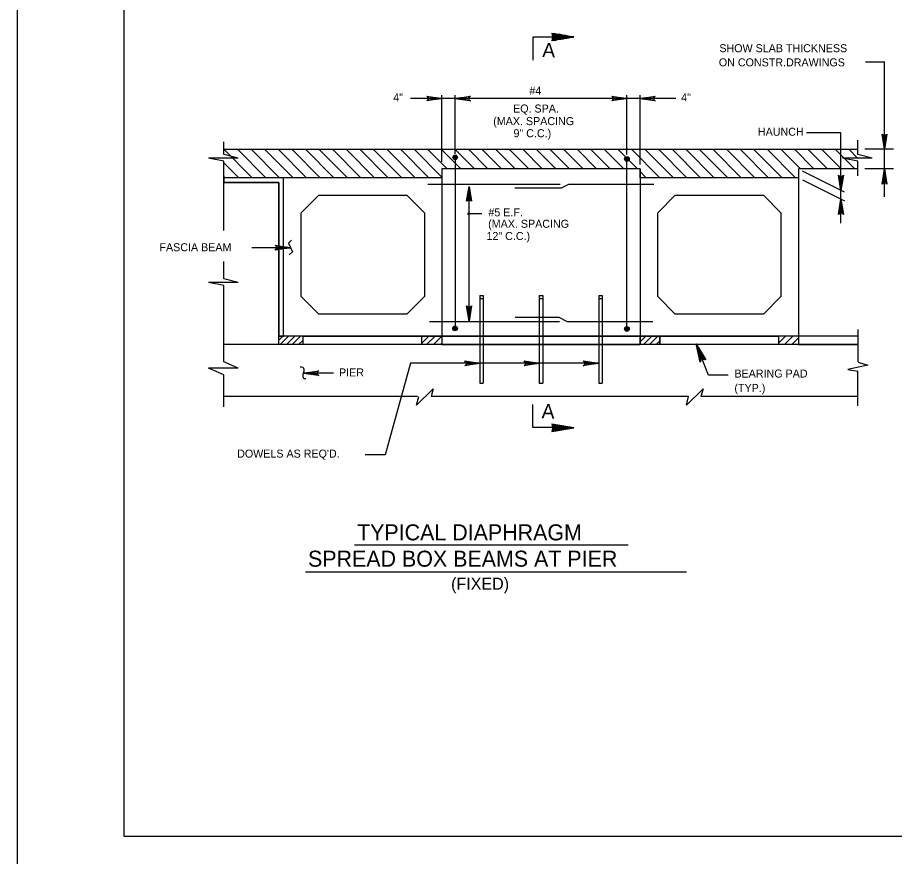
# Model space of a CAD drawing. Extents: x 641517 to 642372, y 298537 to 300319.
# Drawn here: x 641517 to 641845.7, y 299732.1 to 300046.6 of the extents above; entities that cross this region are included whole.
import ezdxf

# ---------------------------------------------------------------- set-up
doc = ezdxf.new("R2010")
doc.units = 0
doc.layers.add('2', color=7, linetype='Continuous')
doc.layers.add('PLT-BNDY', color=7, linetype='Continuous')

msp = doc.modelspace()

# ---------------------------------------------------------------- linework, layer by layer
at = {"layer": '2'}
for p, q in [((641557.05, 299739.62), (641557.05, 300303.62)), ((641722.01, 300039.19), (641710.17, 300039.22)), ((641710.17, 300039.22), (641710.17, 300030.64)), ((641834.82, 300029.95), (641841.96, 300029.95)), ((641841.96, 299997.22), (641841.96, 300029.95)), ((641681.07, 300016.27), (641664.27, 300016.27)), ((641676.12, 299992.57), (641676.12, 300017.47)), ((641681.07, 299995.57), (641681.07, 300017.47)), ((641745.42, 300016.27), (641681.07, 300016.27)), ((641745.42, 299995.27), (641745.42, 300017.47)), ((641763.72, 300016.27), (641745.42, 300016.27)), ((641750.37, 299991.52), (641750.37, 300017.47)), ((641825.67, 300003.45), (641812.71, 300003.45)), ((641825.67, 299969.47), (641825.67, 300003.45)), ((641594.37, 299995.27), (641594.37, 300000.07)), ((641831.97, 299995.27), (641831.97, 300000.67)), ((641594.37, 299997.22), (641831.97, 299997.22)), ((641594.37, 299997.22), (641594.37, 299997.22)), ((641594.37, 299997.22), (641605.02, 299986.57)), ((641599.46, 299997.22), (641610.11, 299986.57)), ((641604.55, 299997.22), (641615.2, 299986.57)), ((641609.64, 299997.22), (641620.29, 299986.57)), ((641614.74, 299997.22), (641625.39, 299986.57)), ((641619.83, 299997.22), (641630.48, 299986.57)), ((641624.92, 299997.22), (641635.57, 299986.57)), ((641630.01, 299997.22), (641640.66, 299986.57)), ((641635.1, 299997.22), (641645.75, 299986.57)), ((641640.19, 299997.22), (641650.84, 299986.57)), ((641645.28, 299997.22), (641655.93, 299986.57)), ((641650.37, 299997.22), (641661.02, 299986.57)), ((641655.46, 299997.22), (641666.11, 299986.57)), ((641660.56, 299997.22), (641671.21, 299986.57)), ((641665.65, 299997.22), (641676.12, 299986.75)), ((641670.74, 299997.22), (641678.09, 299989.87)), ((641675.83, 299997.22), (641683.18, 299989.87)), ((641680.92, 299997.22), (641688.27, 299989.87)), ((641686.01, 299997.22), (641693.36, 299989.87)), ((641691.1, 299997.22), (641698.45, 299989.87)), ((641696.19, 299997.22), (641703.54, 299989.87)), ((641701.29, 299997.22), (641708.64, 299989.87)), ((641706.38, 299997.22), (641713.73, 299989.87)), ((641711.47, 299997.22), (641718.82, 299989.87)), ((641716.56, 299997.22), (641723.91, 299989.87)), ((641721.65, 299997.22), (641729, 299989.87)), ((641726.74, 299997.22), (641734.09, 299989.87)), ((641731.83, 299997.22), (641739.18, 299989.87)), ((641736.92, 299997.22), (641744.27, 299989.87)), ((641742.01, 299997.22), (641749.36, 299989.87)), ((641747.11, 299997.22), (641757.76, 299986.57)), ((641752.2, 299997.22), (641762.85, 299986.57)), ((641757.29, 299997.22), (641767.94, 299986.57)), ((641762.38, 299997.22), (641773.03, 299986.57)), ((641767.47, 299997.22), (641778.12, 299986.57)), ((641772.56, 299997.22), (641783.21, 299986.57)), ((641777.65, 299997.22), (641788.3, 299986.57)), ((641782.74, 299997.22), (641793.39, 299986.57)), ((641787.84, 299997.22), (641798.49, 299986.57)), ((641792.93, 299997.22), (641803.58, 299986.57)), ((641798.02, 299997.22), (641808.67, 299986.57)), ((641803.11, 299997.22), (641810.46, 299989.87)), ((641808.2, 299997.22), (641815.55, 299989.87)), ((641813.29, 299997.22), (641820.64, 299989.87)), ((641818.38, 299997.22), (641825.73, 299989.87)), ((641823.47, 299997.22), (641830.82, 299989.87)), ((641828.56, 299997.22), (641831.97, 299993.82)), ((641845.32, 299997.22), (641834.61, 299997.22)), ((641841.96, 299989.87), (641841.96, 299997.22)), ((641599.77, 299993.92), (641588.67, 299993.92)), ((641594.37, 299992.72), (641588.67, 299993.92)), ((641599.77, 299993.92), (641594.37, 299995.27)), ((641594.37, 299986.57), (641594.37, 299992.72)), ((641681.07, 299994.07), (641681.07, 299930.02)), ((641745.42, 299929.87), (641745.42, 299993.62)), ((641837.37, 299993.92), (641826.27, 299993.92)), ((641831.97, 299992.72), (641826.27, 299993.92)), ((641837.37, 299993.92), (641831.97, 299995.27)), ((641831.97, 299987.32), (641831.97, 299992.72)), ((641594.37, 299992.13), (641599.93, 299986.57)), ((641676.12, 299989.87), (641676.12, 299924.02)), ((641750.37, 299989.87), (641676.12, 299989.87)), ((641676.12, 299989.87), (641676.12, 299986.57)), ((641750.37, 299989.87), (641750.37, 299924.02)), ((641750.37, 299986.57), (641750.37, 299989.87)), ((641831.97, 299989.87), (641809.77, 299989.87)), ((641809.77, 299989.87), (641809.77, 299986.57)), ((641811.12, 299989.12), (641826.87, 299981.32)), ((641845.32, 299989.87), (641834.61, 299989.87)), ((641841.96, 299979.37), (641841.96, 299989.87)), ((641594.37, 299987.04), (641594.84, 299986.57)), ((641616.72, 299986.57), (641594.37, 299986.57)), ((641594.37, 299966.76), (641594.37, 299986.57)), ((641616.72, 299927.17), (641616.72, 299986.57)), ((641676.12, 299986.57), (641616.72, 299986.57)), ((641616.72, 299986.57), (641616.72, 299986.57)), ((641750.37, 299988.87), (641752.66, 299986.57)), ((641809.77, 299986.57), (641750.37, 299986.57)), ((641809.77, 299986.57), (641809.77, 299924.02)), ((641811.27, 299985.82), (641827.02, 299977.87)), ((641614.92, 299984.77), (641594.37, 299984.77)), ((641614.92, 299924.02), (641614.92, 299984.77)), ((641720.39, 299984.02), (641670.87, 299984.02)), ((641686.27, 299932.54), (641686.27, 299983.27)), ((641720.74, 299982.63), (641703.42, 299982.63)), ((641723.52, 299984.02), (641720.74, 299982.63)), ((641755.47, 299984.02), (641723.52, 299984.02)), ((641623.32, 299973.37), (641629.92, 299979.97)), ((641629.92, 299979.97), (641662.92, 299979.97)), ((641662.92, 299979.97), (641669.52, 299973.37)), ((641756.97, 299973.37), (641763.57, 299979.97)), ((641763.57, 299979.97), (641796.57, 299979.97)), ((641796.57, 299979.97), (641803.17, 299973.37)), ((641623.32, 299942.02), (641623.32, 299973.37)), ((641669.52, 299973.37), (641669.52, 299942.02)), ((641691.04, 299973.05), (641686.21, 299973.05)), ((641688.37, 299973.05), (641686.21, 299973.05)), ((641688.37, 299973.05), (641686.21, 299973.05)), ((641688.37, 299973.05), (641686.21, 299973.05)), ((641756.97, 299942.02), (641756.97, 299973.37)), ((641803.17, 299973.37), (641803.17, 299942.02)), ((641619.3, 299960.32), (641604.87, 299960.32)), ((641594.37, 299948.67), (641594.37, 299955.18)), ((641594.37, 299948.67), (641594.37, 299953.47)), ((641599.77, 299947.32), (641588.67, 299947.32)), ((641594.37, 299946.12), (641588.67, 299947.32)), ((641599.77, 299947.32), (641594.37, 299948.67)), ((641594.37, 299917.57), (641594.37, 299946.12)), ((641623.32, 299942.02), (641629.92, 299935.42)), ((641669.52, 299942.02), (641662.92, 299935.42)), ((641690.37, 299942.47), (641691.57, 299942.47)), ((641690.37, 299942.47), (641690.37, 299923.54)), ((641690.37, 299941.27), (641691.57, 299941.27)), ((641691.57, 299942.47), (641691.57, 299923.66)), ((641712.57, 299942.47), (641713.92, 299942.47)), ((641712.57, 299942.47), (641712.57, 299923.01)), ((641712.57, 299941.27), (641713.92, 299941.27)), ((641713.92, 299942.47), (641713.92, 299923.01)), ((641734.92, 299942.47), (641736.12, 299942.47)), ((641734.92, 299942.47), (641734.92, 299923.78)), ((641734.92, 299941.27), (641736.12, 299941.27)), ((641736.12, 299942.47), (641736.12, 299924.02)), ((641756.97, 299942.02), (641763.57, 299935.42)), ((641803.17, 299942.02), (641796.57, 299935.42)), ((641662.92, 299935.42), (641629.92, 299935.42)), ((641720.03, 299934.13), (641703.57, 299934.13)), ((641723.22, 299932.54), (641720.03, 299934.13)), ((641796.57, 299935.42), (641763.57, 299935.42)), ((641720.13, 299932.54), (641671.47, 299932.54)), ((641755.17, 299932.54), (641723.22, 299932.54)), ((641676.12, 299927.17), (641614.92, 299927.17)), ((641616.44, 299927.16), (641614.92, 299925.64)), ((641618.64, 299927.16), (641615.49, 299924.01)), ((641617.81, 299924.01), (641620.96, 299927.16)), ((641623.09, 299927.16), (641619.94, 299924.01)), ((641624.07, 299924.02), (641624.07, 299927.17)), ((641624.07, 299927.17), (641668.62, 299927.17)), ((641668.62, 299924.02), (641668.62, 299927.17)), ((641671.19, 299927.17), (641668.62, 299924.6)), ((641668.93, 299927.15), (641668.62, 299926.84)), ((641673.53, 299927.17), (641670.37, 299924.01)), ((641676.11, 299927.15), (641672.97, 299924.01)), ((641750.37, 299927.17), (641676.12, 299927.17)), ((641832.12, 299927.17), (641750.37, 299927.17)), ((641750.39, 299925.05), (641752.48, 299927.14)), ((641754.76, 299927.16), (641751.59, 299923.99)), ((641757.03, 299927.18), (641753.84, 299923.99)), ((641757.72, 299924.02), (641757.72, 299927.17)), ((641757.72, 299927.17), (641802.27, 299927.17)), ((641802.42, 299924.02), (641802.42, 299927.15)), ((641804.84, 299927.18), (641802.45, 299924.78)), ((641807.66, 299927.18), (641804.51, 299924.03)), ((641809.77, 299926.59), (641807.21, 299924.03)), ((641832.12, 299917.49), (641832.12, 299929.72)), ((641832.11, 299924.02), (641594.37, 299924.02)), ((641624.07, 299925.68), (641622.39, 299924)), ((641676.11, 299924.6), (641675.53, 299924.02)), ((641690.37, 299923.54), (641690.37, 299909.51)), ((641691.57, 299923.66), (641691.57, 299909.51)), ((641712.57, 299923.54), (641712.57, 299909.51)), ((641713.92, 299923.54), (641713.92, 299909.51)), ((641734.92, 299923.78), (641734.92, 299909.51)), ((641736.12, 299924.02), (641736.12, 299909.51)), ((641756.44, 299924.01), (641757.69, 299925.25)), ((641776.06, 299912.53), (641771.37, 299924.33)), ((641599.77, 299915.21), (641594.37, 299917.52)), ((641664.37, 299916.99), (641654.82, 299882.66)), ((641689.62, 299916.99), (641664.37, 299916.99)), ((641711.97, 299916.99), (641690.07, 299916.99)), ((641734.92, 299916.99), (641711.97, 299916.99)), ((641599.77, 299915.21), (641588.67, 299915.21)), ((641594.37, 299912.66), (641588.67, 299915.21)), ((641831.97, 299901.11), (641831.97, 299914.01)), ((641594.37, 299900.66), (641594.37, 299912.66)), ((641635.47, 299913.26), (641624.37, 299913.26)), ((641690.97, 299910.26), (641690.97, 299910.26)), ((641713.17, 299910.26), (641713.17, 299910.26)), ((641735.52, 299910.26), (641735.52, 299910.26)), ((641783.41, 299912.53), (641776.06, 299912.53)), ((641666.52, 299901.26), (641672.82, 299907.41)), ((641672.82, 299907.41), (641672.07, 299904.56)), ((641690.37, 299909.51), (641691.57, 299909.51)), ((641712.57, 299909.51), (641713.92, 299909.51)), ((641734.92, 299909.51), (641736.12, 299909.51)), ((641767.77, 299901.26), (641774.07, 299907.41)), ((641774.07, 299907.41), (641773.17, 299904.56)), ((641666.97, 299904.56), (641594.37, 299904.56)), ((641666.52, 299901.26), (641667.42, 299904.56)), ((641768.52, 299904.56), (641672.07, 299904.56)), ((641767.77, 299901.26), (641768.52, 299904.56)), ((641831.97, 299904.56), (641773.17, 299904.56)), ((641710.17, 299892.93), (641710.17, 299901.5)), ((641722.01, 299892.96), (641710.17, 299892.93)), ((641654.82, 299882.66), (641647.37, 299882.66)), ((641643.29, 299849), (641745.91, 299849)), ((641624.91, 299838.87), (641767.79, 299838.87)), ((642343.05, 299739.62), (641557.05, 299739.62))]:
    msp.add_line(p, q, dxfattribs=at)
for points in [[(641717.35, 300040.69), (641725.52, 300039.32), (641717.34, 300037.93), (641717.42, 300038.13), (641718.28, 300037.99), (641719.31, 300038.25), (641717.5, 300038.32), (641717.58, 300038.52), (641720.68, 300038.48), (641721.76, 300038.6), (641717.53, 300038.66), (641717.61, 300038.85), (641722.93, 300038.91), (641724.15, 300039.09), (641717.69, 300039.05), (641717.64, 300039.19), (641725.24, 300039.21), (641725.52, 300039.32), (641724.46, 300039.54), (641717.72, 300039.38), (641717.61, 300039.66), (641723.45, 300039.61), (641722.4, 300039.83), (641717.69, 300039.85), (641717.63, 300039.99), (641721.34, 300040.04), (641720.08, 300040.34), (641717.52, 300040.27), (641717.46, 300040.41), (641719.08, 300040.42), (641717.88, 300040.58), (641717.4, 300040.55)], [(641670.72, 300016.87), (641670.87, 300016.57), (641676.12, 300016.27), (641670.72, 300016.87), (641670.42, 300017.17), (641676.12, 300016.27), (641670.87, 300015.97), (641670.72, 300015.67), (641676.12, 300016.27), (641670.42, 300015.37), (641670.72, 300015.67)], [(641686.47, 300015.52), (641686.32, 300015.97), (641681.07, 300016.27), (641686.47, 300015.52), (641686.77, 300015.37), (641681.07, 300016.27), (641686.32, 300016.57), (641686.47, 300016.87), (641681.07, 300016.27), (641686.77, 300017.17), (641686.47, 300016.87)], [(641740.02, 300016.87), (641740.17, 300016.57), (641745.42, 300016.27), (641740.02, 300016.87), (641739.72, 300017.17), (641745.42, 300016.27), (641740.17, 300015.97), (641740.02, 300015.67), (641745.42, 300016.27), (641739.72, 300015.37), (641740.02, 300015.67)], [(641755.77, 300015.52), (641755.62, 300015.97), (641750.37, 300016.27), (641755.77, 300015.52), (641756.07, 300015.37), (641750.37, 300016.27), (641755.62, 300016.57), (641755.77, 300016.87), (641750.37, 300016.27), (641756.07, 300017.17), (641755.77, 300016.87)], [(641842.71, 300002.62), (641842.26, 300002.47), (641841.96, 299997.22), (641842.71, 300002.62), (641842.86, 300002.92), (641841.96, 299997.22), (641841.66, 300002.47), (641841.36, 300002.62), (641841.96, 299997.22), (641841.06, 300002.92), (641841.36, 300002.62)], [(641594.37, 299997.22), (641594.52, 299997.22)], [(641831.97, 299989.87), (641831.97, 299989.87)], [(641841.36, 299984.47), (641841.66, 299984.77), (641841.96, 299989.87), (641841.36, 299984.47), (641841.06, 299984.17), (641841.96, 299989.87), (641842.26, 299984.77), (641842.56, 299984.47), (641841.96, 299989.87), (641842.86, 299984.17), (641842.56, 299984.47)], [(641826.42, 299987.17), (641825.97, 299987.02), (641825.67, 299981.77), (641826.42, 299987.17), (641826.57, 299987.47), (641825.67, 299981.77), (641825.37, 299987.02), (641825.07, 299987.17), (641825.67, 299981.77), (641824.77, 299987.47), (641825.07, 299987.17)], [(641685.52, 299977.87), (641685.97, 299978.17), (641686.27, 299983.27), (641685.52, 299977.87), (641685.37, 299977.72), (641686.27, 299983.27), (641686.42, 299978.17), (641686.87, 299978.02), (641686.27, 299983.27), (641687.17, 299977.72), (641686.87, 299978.02)], [(641825.07, 299973.07), (641825.37, 299973.37), (641825.67, 299978.47), (641825.07, 299973.07), (641824.77, 299972.77), (641825.67, 299978.47), (641825.97, 299973.37), (641826.27, 299973.07), (641825.67, 299978.47), (641826.57, 299972.77), (641826.27, 299973.07)], [(641619.75, 299963.15), (641618.59, 299961.99), (641620.07, 299958.72), (641618.91, 299957.67)], [(641613.9, 299961.07), (641614.2, 299960.62), (641619.3, 299960.32), (641613.9, 299961.07), (641613.6, 299961.22), (641619.3, 299960.32), (641614.2, 299960.02), (641613.9, 299959.72), (641619.3, 299960.32), (641613.6, 299959.42), (641613.9, 299959.72)], [(641686.87, 299938.24), (641686.57, 299938.09), (641686.27, 299932.84), (641686.87, 299938.24), (641687.17, 299938.54), (641686.27, 299932.84), (641685.97, 299938.09), (641685.52, 299938.24), (641686.27, 299932.84), (641685.37, 299938.54), (641685.52, 299938.24)], [(641773.05, 299917.85), (641773.4, 299918.26), (641771.37, 299924.33), (641773.05, 299917.85), (641772.9, 299917.43), (641771.37, 299924.33), (641774.02, 299918.51), (641774.55, 299918.47), (641771.37, 299924.33), (641774.98, 299918.25), (641774.55, 299918.47)], [(641684.97, 299917.59), (641685.27, 299917.14), (641690.37, 299916.99), (641684.97, 299917.59), (641684.67, 299917.89), (641690.37, 299916.99), (641685.27, 299916.69), (641684.97, 299916.24), (641690.37, 299916.99), (641684.67, 299916.09), (641684.97, 299916.24)], [(641707.17, 299917.59), (641707.32, 299917.14), (641712.57, 299916.99), (641707.17, 299917.59), (641706.87, 299917.89), (641712.57, 299916.99), (641707.32, 299916.69), (641707.17, 299916.24), (641712.57, 299916.99), (641706.87, 299916.09), (641707.17, 299916.24)], [(641729.37, 299917.59), (641729.52, 299917.14), (641734.77, 299916.99), (641729.37, 299917.59), (641729.07, 299917.89), (641734.77, 299916.99), (641729.52, 299916.69), (641729.37, 299916.24), (641734.77, 299916.99), (641729.07, 299916.09), (641729.37, 299916.24)], [(641832.12, 299917.46), (641835.72, 299916.26), (641828.22, 299914.61), (641832.12, 299914.01)], [(641629.77, 299912.51), (641629.47, 299912.96), (641624.37, 299913.26), (641629.77, 299912.51), (641629.92, 299912.36), (641624.37, 299913.26), (641629.47, 299913.41), (641629.62, 299913.86), (641624.37, 299913.26), (641629.92, 299914.16), (641629.62, 299913.86)], [(641717.35, 299891.46), (641725.52, 299892.83), (641717.34, 299894.22), (641717.42, 299894.02), (641718.28, 299894.15), (641719.31, 299893.9), (641717.5, 299893.83), (641717.58, 299893.63), (641720.68, 299893.67), (641721.76, 299893.55), (641717.53, 299893.49), (641717.61, 299893.3), (641722.93, 299893.23), (641724.15, 299893.06), (641717.69, 299893.1), (641717.64, 299892.96), (641725.24, 299892.94), (641725.52, 299892.83), (641724.46, 299892.61), (641717.72, 299892.77), (641717.61, 299892.49), (641723.45, 299892.53), (641722.4, 299892.32), (641717.69, 299892.29), (641717.63, 299892.15), (641721.34, 299892.1), (641720.08, 299891.8), (641717.52, 299891.88), (641717.46, 299891.74), (641719.08, 299891.73), (641717.88, 299891.57), (641717.4, 299891.6)]]:
    msp.add_lwpolyline(points, dxfattribs=at)
for points in [[(641594.37, 299986.57), (641594.37, 299984.77), (641614.92, 299984.77), (641614.92, 299927.17), (641616.72, 299927.17), (641616.72, 299986.57)], [(641668.62, 299927.17), (641757.72, 299927.17), (641757.72, 299924.02), (641668.62, 299924.02)], [(641676.12, 299927.17), (641676.12, 299924.02), (641750.37, 299924.02), (641750.37, 299927.17)], [(641809.77, 299924.02), (641832.11, 299924.02), (641832.12, 299927.17), (641809.77, 299927.17)]]:
    msp.add_lwpolyline(points, close=True, dxfattribs=at)
for centre, radius in [((641681.06, 299994.21), 0.867), ((641681.06, 299994.21), 0.619), ((641681.06, 299994.21), 0.339), ((641681.07, 299994.14), 0.309), ((641681.06, 299994.21), 0.171), ((641681.06, 299994.21), 0.0732), ((641745.42, 299993.62), 0.867), ((641745.42, 299993.62), 0.619), ((641745.42, 299993.62), 0.339), ((641745.42, 299993.62), 0.171), ((641745.42, 299993.62), 0.0732), ((641686.21, 299973.05), 0.332), ((641686.21, 299973.05), 0.332), ((641686.21, 299973.05), 0.332), ((641686.21, 299973.05), 0.332), ((641681.03, 299930.08), 0.867), ((641681.03, 299930.08), 0.619), ((641681.03, 299930.08), 0.339), ((641681.03, 299930.08), 0.171), ((641681.03, 299930.08), 0.0732), ((641745.42, 299929.87), 0.867), ((641745.42, 299929.87), 0.619), ((641745.42, 299929.87), 0.339), ((641745.42, 299929.87), 0.171), ((641745.42, 299929.87), 0.0732)]:
    msp.add_circle(centre, radius, dxfattribs=at)
for centre, start, end in [((641713.86, 300039.32), 337.8221, 22.0698), ((641713.86, 299892.83), 337.9302, 22.1779)]:
    msp.add_arc(centre, 3.8, start, end, dxfattribs=at)
msp.add_spline([(641623.02, 299915.66), (641623.92, 299915.51), (641624.22, 299915.21), (641624.37, 299914.46), (641624.22, 299913.71), (641624.07, 299913.11), (641623.92, 299912.36), (641624.07, 299911.61), (641624.52, 299911.31), (641625.12, 299911.31)], degree=3, dxfattribs=at)
at = {"layer": 'PLT-BNDY'}
msp.add_lwpolyline([(641517.05, 300318.62), (642358.05, 300318.62), (642358.05, 299724.62), (641517.05, 299724.62)], close=True, dxfattribs=at)

# ---------------------------------------------------------------- texts
at = {"layer": '2'}
for p in [(641713.66, 300031.78), (641713.42, 299896.4)]:
    msp.add_text('A', height=5.4, rotation=358.1262, dxfattribs=at).set_placement(p)
for s, height, p in [('SHOW SLAB THICKNESS', 2.9988, (641780.08, 300033.61)), ('ON CONSTR.DRAWINGS', 2.9988, (641779.89, 300028.31)), ('#4', 3, (641708.87, 300017.7)), ('4"', 3, (641657.85, 300015.17)), ('4"', 3, (641765.77, 300015.17)), ('EQ. SPA.', 3, (641702.77, 300011)), ('(MAX. SPACING', 3, (641695.33, 300006.29)), ('9" C.C.)', 3, (641702.93, 300001.74)), ('HAUNCH', 2.999, (641794.53, 300002.3)), ('#5 E.F.', 3, (641693.52, 299972.08)), ('(MAX. SPACING', 3, (641693.43, 299967.8)), ('12" C.C.)', 3, (641692.8, 299963.21)), ('FASCIA BEAM', 2.9988, (641570.24, 299959)), ('PIER', 2.999, (641637.54, 299912.08)), ('BEARING PAD', 2.9988, (641785.73, 299911.66)), ('(TYP.)', 2.999, (641785.73, 299906.26)), ("DOWELS AS REQ'D.", 2.9988, (641599.35, 299881.64)), ('TYPICAL DIAPHRAGM', 6, (641644.29, 299850.62)), ('SPREAD BOX BEAMS AT PIER', 6, (641625.91, 299840.75)), ('(FIXED)', 4.5, (641679.54, 299832.12))]:
    msp.add_text(s, height=height, dxfattribs=at).set_placement(p)

doc.saveas('drawing.dxf')
